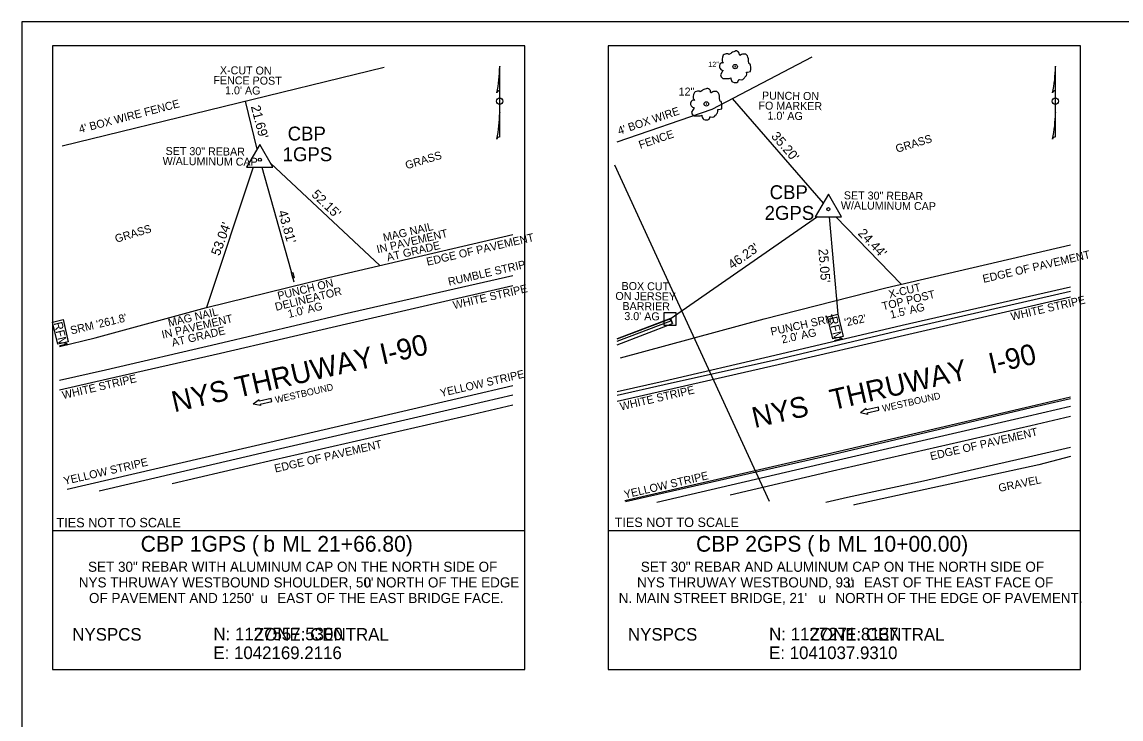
# Model space of a CAD drawing. Extents: x 1042984 to 1043775, y 1125614 to 1126116.
# Drawn here: x 1042984.3 to 1043379.9, y 1125865.1 to 1126116 of the extents above; entities that cross this region are included whole.
import ezdxf

# ---------------------------------------------------------------- set-up
doc = ezdxf.new("R2010")
doc.units = 0
for name, color, linetype in [('CB', 7, 'Continuous'), ('CBP', 7, 'Continuous'), ('CBP_C', 7, 'Continuous'), ('CBT', 7, 'Continuous'), ('CPBM', 7, 'Continuous'), ('Default', 7, 'Continuous'), ('LFNC', 7, 'Continuous'), ('LFNC_C', 7, 'Continuous'), ('LTD', 7, 'Continuous'), ('LTD_C', 7, 'Continuous'), ('LUKP_C', 7, 'Continuous'), ('NNA_P', 7, 'Continuous'), ('PE', 7, 'Continuous'), ('PE_C', 7, 'Continuous'), ('PET', 7, 'Continuous'), ('PSU', 7, 'Continuous'), ('RC_C', 7, 'Continuous'), ('RDU_C', 7, 'Continuous'), ('RELB', 7, 'Continuous'), ('RGB', 7, 'Continuous'), ('RGWM', 7, 'Continuous'), ('RRS', 7, 'Continuous'), ('RRS_C', 7, 'Continuous'), ('SDEL', 7, 'Continuous'), ('STSEW', 7, 'Continuous'), ('STSEW_I', 7, 'Continuous'), ('STSEY', 7, 'Continuous'), ('STSEY_C', 7, 'Continuous'), ('UEO', 7, 'Continuous')]:
    doc.layers.add(name, color=color, linetype=linetype)

# ---------------------------------------------------------------- blocks, each defined once
blk = doc.blocks.new('NNAM')
at = {"layer": 'NNA_P'}
for p, q in [((0, 0.0147), (0, 0.0501)), ((0, 0.0496), (0, 0.0496)), ((0, 0.0496), (0, 0.0496)), ((0, -0.0004), (0, 0.0147)), ((0, -0.0168), (0, -0.0004)), ((0, -0.0166), (0, -0.0168)), ((0, -0.0172), (0, -0.0168)), ((0, -0.0518), (0, -0.0172))]:
    blk.add_line(p, q, dxfattribs=at)
blk.add_circle((0, -0.0003), 0.00455, dxfattribs=at)
for centre, radius, start, end in [((-0.1834, 0.0501), 0.1834, 347.8839, 359.8678), ((0.1834, 0.0501), 0.1834, 179.9909, 180.1322), ((0, 0.0105), 0.00425, 90.435, 165.5809), ((-0.1834, -0.0164), 0.1834, 347.8839, 359.8678), ((0.1834, -0.0164), 0.1834, 179.9909, 180.1322), ((-0.1834, -0.0164), 0.1834, 359.9196, 0.009), ((0, -0.056), 0.00424, 90.0107, 164.1061)]:
    blk.add_arc(centre, radius, start, end, dxfattribs=at)
blk = doc.blocks.new('SRM')
at = {"layer": 'Default'}
blk.add_lwpolyline([(-1.36, 0.66), (1.37, 0.66), (1.37, -0.63), (-1.36, -0.63)], close=True, dxfattribs=at)
blk.add_text('RFM', height=1.033, dxfattribs=at).set_placement((-1.23, -0.52))

msp = doc.modelspace()

# ---------------------------------------------------------------- linework, layer by layer
at = {"layer": 'CB'}
for p, q in [((1042995.27, 1125932.94), (1043165.27, 1125932.94)), ((1043195.27, 1125932.94), (1043365.27, 1125932.94))]:
    msp.add_line(p, q, dxfattribs=at)
for points in [[(1042984.33, 1125614.24), (1043775.43, 1125614.24), (1043775.43, 1126116.03), (1042984.33, 1126116.03)], [(1043165.27, 1125882.94), (1043165.27, 1126107.4), (1042995.27, 1126107.4), (1042995.27, 1125882.94)], [(1043365.27, 1125882.94), (1043365.27, 1126107.4), (1043195.27, 1126107.4), (1043195.27, 1125882.94)]]:
    msp.add_lwpolyline(points, close=True, dxfattribs=at)
at = {"layer": 'CBP'}
for points in [[(1043069.92, 1126071.92), (1043065.19, 1126063.74)], [(1043074.64, 1126063.74), (1043069.92, 1126071.92)], [(1043065.19, 1126063.74), (1043074.64, 1126063.74)], [(1043274.56, 1126054.09), (1043269.84, 1126045.91)], [(1043279.29, 1126045.91), (1043274.56, 1126054.09)], [(1043269.84, 1126045.91), (1043279.29, 1126045.91)]]:
    msp.add_lwpolyline(points, dxfattribs=at)
for centre in [(1043069.92, 1126066.46), (1043274.56, 1126048.64)]:
    msp.add_circle(centre, 0.564, dxfattribs=at)
at = {"layer": 'CBT'}
for p, q in [((1043068.98, 1126070.29), (1043064.75, 1126087.57)), ((1043239.97, 1126088.52), (1043272.67, 1126050.82)), ((1043067.57, 1126063.74), (1043050.74, 1126013.23)), ((1043070.68, 1126063.74), (1043080.94, 1126027.05)), ((1043073.78, 1126065.24), (1043113.14, 1126028.41)), ((1043270.64, 1126045.91), (1043217.6, 1126009.1)), ((1043274.81, 1126045.91), (1043278.02, 1126010.81)), ((1043277.21, 1126045.91), (1043300.78, 1126021.65))]:
    msp.add_line(p, q, dxfattribs=at)
at = {"layer": 'CPBM'}
msp.add_lwpolyline([(1043215.38, 1126006.87), (1043219.83, 1126006.87), (1043219.83, 1126011.32), (1043215.38, 1126011.32)], close=True, dxfattribs=at)
for points in [[(1043217.47, 1126008.97), (1043217.73, 1126009.23)], [(1043217.47, 1126009.23), (1043217.73, 1126008.97)], [(1043217.6, 1126009.1), (1043217.6, 1126009.1)]]:
    msp.add_lwpolyline(points, dxfattribs=at)
msp.add_circle((1043217.6, 1126009.1), 0.183, dxfattribs=at)
at = {"layer": 'LFNC'}
for points in [[(1043198.59, 1126072.84), (1043232.75, 1126084.66), (1043268.69, 1126103.54)], [(1042998.78, 1126071.41), (1043114.63, 1126099.79)]]:
    msp.add_lwpolyline(points, dxfattribs=at)
at = {"layer": 'LTD'}
for points in [[(1043246.39, 1126100.88), (1043245.99, 1126101.03), (1043245.85, 1126101.21), (1043245.9, 1126101.34), (1043245.81, 1126101.98), (1043245.81, 1126102.82), (1043245.62, 1126103.41), (1043245.4, 1126103.86), (1043244.85, 1126104.41), (1043244.45, 1126104.5), (1043243.65, 1126104.41), (1043243.33, 1126104.32), (1043242.75, 1126104), (1043242.65, 1126103.95), (1043242.56, 1126104.27), (1043242.47, 1126104.77), (1043242.16, 1126105.22), (1043241.84, 1126105.45), (1043241.57, 1126105.59), (1043241.2, 1126105.59), (1043240.93, 1126105.45), (1043240.48, 1126105.31), (1043240.11, 1126105.22), (1043239.66, 1126104.95), (1043239.43, 1126104.68), (1043238.78, 1126104.27), (1043238.46, 1126104.54), (1043237.82, 1126104.54), (1043237.05, 1126104.27), (1043236.74, 1126104.04), (1043236.42, 1126103.34), (1043236.33, 1126102.66), (1043236.33, 1126102.03), (1043236.51, 1126101.57), (1043236.74, 1126101.21)], [(1043236.74, 1126101.21), (1043236.06, 1126101.3), (1043235.51, 1126100.85), (1043235.33, 1126100.26), (1043235.33, 1126099.8), (1043235.51, 1126099.35), (1043236.01, 1126098.85), (1043236.37, 1126098.67), (1043236.69, 1126098.58), (1043236.46, 1126098.31), (1043236.28, 1126098.03), (1043235.74, 1126097.06), (1043235.92, 1126096.24), (1043236.6, 1126095.7), (1043237.05, 1126095.65), (1043238.01, 1126095.65), (1043238.82, 1126095.7), (1043239.43, 1126095.88), (1043239.43, 1126095.56), (1043239.66, 1126094.93), (1043239.84, 1126094.61), (1043240.11, 1126094.43), (1043240.61, 1126094.25), (1043241.25, 1126094.2), (1043241.57, 1126094.25), (1043242.02, 1126094.52), (1043242.25, 1126095.11), (1043242.29, 1126095.34), (1043242.56, 1126095.29), (1043243.2, 1126095.2), (1043243.74, 1126095.34), (1043243.92, 1126095.47), (1043244.38, 1126095.93), (1043244.51, 1126096.11), (1043244.85, 1126096.51), (1043245.04, 1126096.79), (1043245.17, 1126097.29), (1043245.13, 1126097.94), (1043245.44, 1126097.99), (1043246.56, 1126098.22)], [(1043241.09, 1126099.98), (1043241.09, 1126099.98), (1043241.09, 1126099.98), (1043241.09, 1126100.01), (1043241.09, 1126100.01), (1043241.09, 1126100.01), (1043241.09, 1126100.03), (1043241.07, 1126100.03), (1043241.07, 1126100.03), (1043241.07, 1126100.03), (1043241.07, 1126100.03), (1043241.07, 1126100.05), (1043241.04, 1126100.05), (1043241.04, 1126100.05), (1043241.04, 1126100.05), (1043241.02, 1126100.05), (1043241.02, 1126100.05), (1043241.02, 1126100.05), (1043241, 1126100.05), (1043241, 1126100.05), (1043241, 1126100.05), (1043240.98, 1126100.05), (1043240.98, 1126100.03), (1043240.98, 1126100.03), (1043240.98, 1126100.03), (1043240.95, 1126100.03), (1043240.95, 1126100.03), (1043240.95, 1126100.01), (1043240.95, 1126100.01), (1043240.95, 1126100.01), (1043240.95, 1126099.98), (1043240.95, 1126099.98), (1043240.95, 1126099.98), (1043240.95, 1126099.96), (1043240.95, 1126099.96), (1043240.95, 1126099.96), (1043240.95, 1126099.94), (1043240.95, 1126099.94), (1043240.98, 1126099.94), (1043240.98, 1126099.94), (1043240.98, 1126099.92), (1043240.98, 1126099.92), (1043241, 1126099.92), (1043241, 1126099.92), (1043241, 1126099.92), (1043241.02, 1126099.92), (1043241.02, 1126099.92), (1043241.02, 1126099.92), (1043241.04, 1126099.92), (1043241.04, 1126099.92), (1043241.04, 1126099.92), (1043241.07, 1126099.92), (1043241.07, 1126099.92), (1043241.07, 1126099.94), (1043241.07, 1126099.94), (1043241.07, 1126099.94), (1043241.09, 1126099.94), (1043241.09, 1126099.96), (1043241.09, 1126099.96), (1043241.09, 1126099.96), (1043241.09, 1126099.98)], [(1043246.56, 1126098.22), (1043246.62, 1126099.08), (1043246.62, 1126099.8), (1043246.53, 1126100.44), (1043246.39, 1126100.88)], [(1043236, 1126087.44), (1043235.6, 1126087.58), (1043235.47, 1126087.77), (1043235.51, 1126087.9), (1043235.42, 1126088.54), (1043235.42, 1126089.38), (1043235.24, 1126089.97), (1043235.01, 1126090.42), (1043234.47, 1126090.96), (1043234.06, 1126091.05), (1043233.27, 1126090.96), (1043232.95, 1126090.87), (1043232.36, 1126090.56), (1043232.27, 1126090.51), (1043232.18, 1126090.83), (1043232.09, 1126091.33), (1043231.77, 1126091.78), (1043231.45, 1126092.01), (1043231.18, 1126092.14), (1043230.82, 1126092.14), (1043230.55, 1126092.01), (1043230.09, 1126091.87), (1043229.73, 1126091.78), (1043229.28, 1126091.51), (1043229.05, 1126091.24), (1043228.39, 1126090.83), (1043228.07, 1126091.1), (1043227.44, 1126091.1), (1043226.67, 1126090.83), (1043226.35, 1126090.6), (1043226.03, 1126089.9), (1043225.94, 1126089.22), (1043225.94, 1126088.58), (1043226.12, 1126088.13), (1043226.35, 1126087.77)], [(1043226.35, 1126087.77), (1043225.67, 1126087.86), (1043225.13, 1126087.4), (1043224.94, 1126086.81), (1043224.94, 1126086.36), (1043225.13, 1126085.91), (1043225.62, 1126085.41), (1043225.99, 1126085.23), (1043226.3, 1126085.14), (1043226.08, 1126084.86), (1043225.9, 1126084.59), (1043225.35, 1126083.62), (1043225.53, 1126082.8), (1043226.21, 1126082.26), (1043226.67, 1126082.21), (1043227.62, 1126082.21), (1043228.44, 1126082.26), (1043229.05, 1126082.44), (1043229.05, 1126082.12), (1043229.28, 1126081.48), (1043229.46, 1126081.17), (1043229.73, 1126080.99), (1043230.23, 1126080.8), (1043230.86, 1126080.76), (1043231.18, 1126080.8), (1043231.63, 1126081.08), (1043231.86, 1126081.67), (1043231.91, 1126081.89), (1043232.18, 1126081.85), (1043232.81, 1126081.76), (1043233.36, 1126081.89), (1043233.54, 1126082.03), (1043233.99, 1126082.48), (1043234.13, 1126082.66), (1043234.47, 1126083.07), (1043234.65, 1126083.34), (1043234.79, 1126083.84), (1043234.74, 1126084.5), (1043235.06, 1126084.55), (1043236.18, 1126084.78)], [(1043230.7, 1126086.54), (1043230.7, 1126086.54), (1043230.7, 1126086.54), (1043230.7, 1126086.56), (1043230.7, 1126086.56), (1043230.7, 1126086.56), (1043230.7, 1126086.59), (1043230.68, 1126086.59), (1043230.68, 1126086.59), (1043230.68, 1126086.59), (1043230.68, 1126086.59), (1043230.68, 1126086.61), (1043230.66, 1126086.61), (1043230.66, 1126086.61), (1043230.66, 1126086.61), (1043230.64, 1126086.61), (1043230.64, 1126086.61), (1043230.64, 1126086.61), (1043230.61, 1126086.61), (1043230.61, 1126086.61), (1043230.61, 1126086.61), (1043230.59, 1126086.61), (1043230.59, 1126086.59), (1043230.59, 1126086.59), (1043230.59, 1126086.59), (1043230.57, 1126086.59), (1043230.57, 1126086.59), (1043230.57, 1126086.56), (1043230.57, 1126086.56), (1043230.57, 1126086.56), (1043230.57, 1126086.54), (1043230.57, 1126086.54), (1043230.57, 1126086.54), (1043230.57, 1126086.52), (1043230.57, 1126086.52), (1043230.57, 1126086.52), (1043230.57, 1126086.5), (1043230.57, 1126086.5), (1043230.59, 1126086.5), (1043230.59, 1126086.5), (1043230.59, 1126086.47), (1043230.59, 1126086.47), (1043230.61, 1126086.47), (1043230.61, 1126086.47), (1043230.61, 1126086.47), (1043230.64, 1126086.47), (1043230.64, 1126086.47), (1043230.64, 1126086.47), (1043230.66, 1126086.47), (1043230.66, 1126086.47), (1043230.66, 1126086.47), (1043230.68, 1126086.47), (1043230.68, 1126086.47), (1043230.68, 1126086.5), (1043230.68, 1126086.5), (1043230.68, 1126086.5), (1043230.7, 1126086.5), (1043230.7, 1126086.52), (1043230.7, 1126086.52), (1043230.7, 1126086.52), (1043230.7, 1126086.54)], [(1043236.18, 1126084.78), (1043236.24, 1126085.63), (1043236.24, 1126086.36), (1043236.15, 1126086.99), (1043236, 1126087.44)]]:
    msp.add_lwpolyline(points, dxfattribs=at)
for centre in [(1043241.02, 1126099.98), (1043230.64, 1126086.54)]:
    msp.add_circle(centre, 0.799, dxfattribs=at)
at = {"layer": 'PE'}
for points in [[(1042997.83, 1125999.26), (1043010.73, 1126002.38), (1043050.74, 1126013.23), (1043094.66, 1126024.05), (1043160.97, 1126039.55)], [(1043038.41, 1125949.93), (1043075.32, 1125958.51), (1043146.69, 1125974.91), (1043160.97, 1125978.23)], [(1043239.17, 1125945.84), (1043276.08, 1125954.42), (1043347.45, 1125970.82), (1043361.73, 1125974.14)]]:
    msp.add_lwpolyline(points, dxfattribs=at)
at = {"layer": 'PET'}
for points in [[(1043198.59, 1125981.7), (1043215.51, 1125985.57), (1043255.84, 1125994.6), (1043301.43, 1126005.37), (1043361.73, 1126019.1)], [(1043201.55, 1125943.43), (1043274.48, 1125959.98), (1043345.46, 1125976.75), (1043361.73, 1125980.48)]]:
    msp.add_lwpolyline(points, dxfattribs=at)
at = {"layer": 'PSU'}
msp.add_lwpolyline([(1043361.73, 1125959.62), (1043350.35, 1125956.59), (1043309.35, 1125947.78), (1043284.02, 1125942.2), (1043283.58, 1125942.11)], dxfattribs=at)
at = {"layer": 'RC_C'}
for p, q in [((1043069.69, 1125980.03), (1043067.59, 1125978.45)), ((1043070.17, 1125977.93), (1043067.59, 1125978.45)), ((1043069.81, 1125979.5), (1043069.69, 1125980.03)), ((1043074.01, 1125980.46), (1043069.81, 1125979.5)), ((1043070.05, 1125978.45), (1043074.25, 1125979.42)), ((1043070.05, 1125978.45), (1043070.17, 1125977.93)), ((1043074.25, 1125979.42), (1043074.01, 1125980.46)), ((1043288.22, 1125976.9), (1043286.12, 1125975.32)), ((1043288.7, 1125974.8), (1043286.12, 1125975.32)), ((1043288.34, 1125976.37), (1043288.22, 1125976.9)), ((1043292.54, 1125977.33), (1043288.34, 1125976.37)), ((1043288.58, 1125975.33), (1043292.77, 1125976.29)), ((1043288.58, 1125975.33), (1043288.7, 1125974.8)), ((1043292.77, 1125976.29), (1043292.54, 1125977.33))]:
    msp.add_line(p, q, dxfattribs=at)
at = {"layer": 'RELB'}
for points in [[(1043198.59, 1126002.04), (1043217.68, 1126009.32)], [(1043198.59, 1125999.78), (1043218.45, 1126007.52), (1043217.73, 1126009.27), (1043198.59, 1126001.95)], [(1043198.59, 1126001.93), (1043217.66, 1126009.18), (1043217.9, 1126008.45)], [(1043198.59, 1126001.15), (1043217.9, 1126008.45)], [(1043217.68, 1126009.32), (1043218.45, 1126007.52)]]:
    msp.add_lwpolyline(points, dxfattribs=at)
at = {"layer": 'RGB'}
msp.add_lwpolyline([(1043199.79, 1125995.09), (1043251.5, 1126009.15), (1043295.26, 1126020.32), (1043361.73, 1126035.79)], dxfattribs=at)
at = {"layer": 'RGWM'}
msp.add_lwpolyline([(1043361.73, 1125962.89), (1043348.12, 1125959.71), (1043308.76, 1125950.74), (1043281.42, 1125944.88), (1043273.6, 1125943.1)], dxfattribs=at)
at = {"layer": 'RRS'}
for points in [[(1042997.83, 1125987.09), (1043014.35, 1125990.88), (1043054.53, 1126000.22), (1043100.32, 1126010.99), (1043160.97, 1126024.75)], [(1043198.59, 1125983.01), (1043215.11, 1125986.79), (1043255.28, 1125996.14), (1043301.07, 1126006.9), (1043361.73, 1126020.66)], [(1043012.12, 1125947.28), (1043074.29, 1125961.79), (1043145.48, 1125978.24), (1043160.97, 1125981.82)], [(1043212.88, 1125943.19), (1043275.05, 1125957.71), (1043346.24, 1125974.16), (1043361.73, 1125977.73)]]:
    msp.add_lwpolyline(points, dxfattribs=at)
at = {"layer": 'SDEL'}
msp.add_line((1043080.94, 1126027.05), (1043082.14, 1126022.48), dxfattribs=at)
msp.add_lwpolyline([(1043081.78, 1126023.84), (1043081.3, 1126025.69), (1043081.85, 1126025.83), (1043082.33, 1126023.99)], close=True, dxfattribs=at)
at = {"layer": 'STSEW'}
for points in [[(1042997.83, 1125983.61), (1043015.17, 1125987.54), (1043055.78, 1125996.84), (1043101.18, 1126007.4), (1043160.97, 1126021.13)], [(1043198.59, 1125979.52), (1043215.93, 1125983.46), (1043256.54, 1125992.76), (1043301.94, 1126003.31), (1043361.73, 1126017.05)]]:
    msp.add_lwpolyline(points, dxfattribs=at)
at = {"layer": 'STSEY'}
for points in [[(1043000.57, 1125947.83), (1043073.49, 1125964.73), (1043144.58, 1125981.37), (1043160.97, 1125985.13)], [(1043201.33, 1125943.74), (1043274.25, 1125960.65), (1043345.33, 1125977.29), (1043361.73, 1125981.05)]]:
    msp.add_lwpolyline(points, dxfattribs=at)
at = {"layer": 'UEO'}
msp.add_lwpolyline([(1043197.64, 1126064.59), (1043253.2, 1125943.6)], dxfattribs=at)

# ---------------------------------------------------------------- block references
at = {"layer": 'CBT', "xscale": 2.9999999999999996, "yscale": 3, "rotation": -76.49801078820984}
for p in [(1043277.05, 1126006.39), (1042998.13, 1126004.47)]:
    msp.add_blockref('SRM', p, dxfattribs=at)
at = {"layer": 'Default', "xscale": 250, "yscale": 250}
for p in [(1043156.27, 1126087.59), (1043356.27, 1126087.59)]:
    msp.add_blockref('NNAM', p, dxfattribs=at)

# ---------------------------------------------------------------- texts
at = {"layer": 'CBP_C'}
for s, height, rotation, p in [("21.69'", 3.402, 284.7544, (1043066.68, 1126085.58)), ("35.20'", 3.402, 310.904, (1043253.77, 1126074.76)), ("52.15'", 3.402, 316.1422, (1043088.28, 1126053.61)), ("43.81'", 3.402, 286.2573, (1043076.43, 1126047.75)), ("53.04'", 3.402, 69.6895, (1043055.44, 1126031.64)), ("24.44'", 3.402, 313.8458, (1043284.98, 1126039.73)), ("46.23'", 3.402, 35.303, (1043239.93, 1126026.85)), ("25.05'", 3.402, 274.4442, (1043270.97, 1126034.28)), ('TIES NOT TO SCALE', 3.4016, 359.9999, (1042996.77, 1125934.13)), ('TIES NOT TO SCALE', 3.4016, 359.9999, (1043197.64, 1125934.24))]:
    msp.add_text(s, height=height, rotation=rotation, dxfattribs=at).set_placement(p)
for s, height, p in [('CBP', 5.002, (1043079.95, 1126073.36)), ('1GPS', 5.002, (1043078.14, 1126065.92)), ('CBP', 5.002, (1043253.42, 1126052.26)), ('2GPS', 5.002, (1043251.61, 1126044.81)), ('CBP 1GPS (', 5.669, (1043027.05, 1125925.36)), ('b', 5.67, (1043071.19, 1125925.36)), (' ML 21+66.80)', 5.6693, (1043075.9, 1125925.36)), ('CBP 2GPS (', 5.669, (1043226.94, 1125925.36)), ('b', 5.67, (1043271.08, 1125925.36)), (' ML 10+00.00)', 5.6693, (1043275.78, 1125925.36)), ('SET 30" REBAR WITH ALUMINUM CAP ON THE NORTH SIDE OF', 3.6284, (1043008.11, 1125918.13)), ('SET 30" REBAR AND ALUMINUM CAP ON THE NORTH SIDE OF', 3.6284, (1043207.05, 1125918.13)), ("NYS THRUWAY WESTBOUND SHOULDER, 50'", 3.6284, (1043004.78, 1125912.5)), ('u', 3.63, (1043107.46, 1125912.5)), (' NORTH OF THE EDGE', 3.6284, (1043110.5, 1125912.5)), ("NYS THRUWAY WESTBOUND, 93'", 3.6284, (1043205.7, 1125912.5)), ('u ', 3.628, (1043281.26, 1125912.5)), ('EAST OF THE EAST FACE OF', 3.6284, (1043287.33, 1125912.5)), ("OF PAVEMENT AND 1250'", 3.6284, (1043008.45, 1125906.88)), ('u ', 3.628, (1043070.15, 1125906.88)), ('EAST OF THE EAST BRIDGE FACE.', 3.6284, (1043076.22, 1125906.88)), ("N. MAIN STREET BRIDGE, 21'", 3.6284, (1043199.09, 1125906.88)), ('u ', 3.628, (1043270.99, 1125906.88)), ('NORTH OF THE EDGE OF PAVEMENT.', 3.6284, (1043277.07, 1125906.88)), ('NYSPCS                        ZONE: CENTRAL', 4.5355, (1043002.44, 1125893.35)), ('N: 1127557.5300', 4.5355, (1043053.23, 1125893.47)), ('NYSPCS                        ZONE: CENTRAL', 4.5355, (1043202.44, 1125893.35)), ('N: 1127271.8137', 4.5355, (1043253.23, 1125893.47)), ('E: 1042169.2116', 4.5355, (1043053.23, 1125886.72)), ('E: 1041037.9310', 4.5355, (1043253.23, 1125886.72))]:
    msp.add_text(s, height=height, dxfattribs=at).set_placement(p)
at = {"layer": 'LFNC_C'}
for s, rotation, p in [('X-CUT ON', 359.4406, (1043055.56, 1126097.25)), ('FENCE POST', 359.4406, (1043053.2, 1126093.66)), ("1.0' AG", 359.4406, (1043057.41, 1126090.02)), ('PUNCH ON', 359.4406, (1043250.65, 1126088.11)), ("4' BOX WIRE FENCE", 14.6207, (1043005.21, 1126076)), ("4' BOX WIRE", 18.759, (1043199.3, 1126075.39)), ('FO MARKER', 359.4406, (1043249.39, 1126084.51)), ("1.0' AG", 359.4406, (1043252.63, 1126080.88)), ('FENCE', 18.759, (1043206.87, 1126070.34)), ('SET 30" REBAR', 359.4406, (1043036.01, 1126068.18)), ('W/ALUMINUM CAP', 359.4406, (1043034.93, 1126064.59)), ('SET 30" REBAR', 359.4406, (1043280.11, 1126052.21)), ('W/ALUMINUM CAP', 359.4406, (1043279.03, 1126048.61)), ('MAG NAIL ', 13.2543, (1043114.65, 1126036.97)), ('IN PAVEMENT', 13.2543, (1043112.35, 1126032.73)), ('AT GRADE', 13.2543, (1043115.96, 1126029.87)), ('PUNCH ON ', 13.8517, (1043076.69, 1126015.98)), ('BOX CUT', 359.4406, (1043200.11, 1126019.57)), ('X-CUT', 13.4243, (1043296.61, 1126016.53)), ('DELINEATOR', 13.8517, (1043075.78, 1126012.04)), ('ON JERSEY ', 359.4406, (1043197.9, 1126015.99)), ('TOP POST', 13.4243, (1043294.22, 1126012.25)), ("1.0' AG", 13.8517, (1043080.41, 1126009.47)), ('BARRIER', 359.4406, (1043200.42, 1126012.36)), ("1.5' AG", 13.4243, (1043297.1, 1126009.23)), ("SRM '261.8'", 13.2823, (1043002.1, 1126003.56)), ('IN PAVEMENT', 13.2543, (1043034.97, 1126002.04)), ('MAG NAIL ', 13.2543, (1043037.27, 1126006.28)), ("3.0' AG", 359.4406, (1043201.11, 1126008.74)), ('PUNCH SRM', 12.2561, (1043254.08, 1126003.14)), ("'262'", 12.2561, (1043280.68, 1126006.41)), ('AT GRADE', 13.2543, (1043038.58, 1125999.18)), ("2.0' AG", 12.2561, (1043258.03, 1126000.31))]:
    msp.add_text(s, height=2.88, rotation=rotation, dxfattribs=at).set_placement(p)
at = {"layer": 'LTD_C'}
for height, p in [(1.876, (1043231.33, 1126099.82)), (2.88, (1043220.67, 1126089.54))]:
    msp.add_text('12"', height=height, dxfattribs=at).set_placement(p)
at = {"layer": 'LUKP_C'}
for p in [(1043299.24, 1126068.94), (1043122.78, 1126062.98), (1043018.28, 1126036.54)]:
    msp.add_text('GRASS', height=2.88, rotation=16.8553, dxfattribs=at).set_placement(p)
at = {"layer": 'PE_C'}
for p in [(1043130.25, 1126028.28), (1043330.45, 1126022.11), (1043311.53, 1125958.27), (1043075.53, 1125953.84)]:
    msp.add_text('EDGE OF PAVEMENT', height=2.88, rotation=13.0884, dxfattribs=at).set_placement(p)
at = {"layer": 'RC_C'}
for s, height, p in [('NYS THRUWAY I-90', 7.5024, (1043039.14, 1125975.51)), ('NYS   THRUWAY   I-90', 7.4428, (1043248.02, 1125969.85)), ('WESTBOUND', 2.461, (1043075.72, 1125978.79)), ('WESTBOUND', 2.461, (1043294.25, 1125975.66))]:
    msp.add_text(s, height=height, rotation=12.8944, dxfattribs=at).set_placement(p)
at = {"layer": 'RDU_C'}
msp.add_text('GRAVEL', height=2.88, rotation=11.824, dxfattribs=at).set_placement((1043336.07, 1125946.84))
at = {"layer": 'RRS_C'}
msp.add_text('RUMBLE STRIP', height=2.88, rotation=13.0884, dxfattribs=at).set_placement((1043138.05, 1126021.07))
at = {"layer": 'STSEW_I'}
for p in [(1043139.81, 1126012.65), (1043340.57, 1126008.56), (1042999.15, 1125980.26), (1043199.91, 1125976.17)]:
    msp.add_text('WHITE STRIPE', height=2.88, rotation=13.0884, dxfattribs=at).set_placement(p)
at = {"layer": 'STSEY_C'}
for p in [(1043135.17, 1125981.05), (1042999.7, 1125949.38), (1043201.37, 1125944.48)]:
    msp.add_text('YELLOW STRIPE', height=2.88, rotation=13.0884, dxfattribs=at).set_placement(p)

doc.saveas('drawing.dxf')
